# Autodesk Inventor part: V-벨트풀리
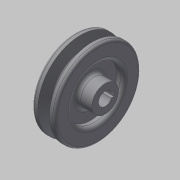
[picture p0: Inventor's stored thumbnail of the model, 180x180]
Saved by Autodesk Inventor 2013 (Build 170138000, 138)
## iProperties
Created: 2015-02
Part Number: V-벨트풀리
Material: 일반
Document SubType Name: Modeling
Designer: Administrator
Density: 1 g/cm^3
Author: Administrator
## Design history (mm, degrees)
sketch "스케치1"
  geometry: L1 (-12.5, 0)-(12.5, 0); L2 (-12.5, 11)-(-6.5, 11); L3 (-6.5, 11)-(-6.5, 21.5); L4 (-6.5, 21.5)-(-12.5, 21.5); L5 (-12.5, 21.5)-(-12.5, 35.2); L6 (-12.5, 35.2)-(-7.825, 35.2); L7 (-7.825, 35.2)-(-5.074, 26.2); L8 (-5.074, 26.2)-(-0.926, 26.2); L9 (-0.926, 26.2)-(1.825, 35.2); L10 (1.825, 35.2)-(6.5, 35.2); L11 (6.5, 35.2)-(6.5, 21.5); L12 (6.5, 21.5)-(0.5, 21.5); L13 (12.5, 5.5)-(-12.5, 5.5); L14 (-12.5, 11)-(-12.5, 5.5); L15 (0.5, 21.5)-(0.5, 11); L16 (0.5, 11)-(12.5, 11); L17 (12.5, 11)-(12.5, 5.5); L18 (-3, 26.2)-(-3, 25.898); L19 (-7, 32.5)-(1, 32.5); L20 (-3, 26.441)-(-3, 35.2); 10 further points
  constraints: 40 end point, 9 midpoint, 9 parallel, 6 perpendicular, 4 vertical alignment, 3 horizontal alignment, 2 coincident, 2 collinear, 2 point on line, 1 horizontal, 1 vertical, 1 other
  dimensions: "d0" = 25 distance of L1.start L1.end; "d2" = 34 deg angle of L9 L7; "d4" = 43 diameter of L4 L1; "d5" = 19 distance between parallel lines of L11 L5; "d6" = 6 distance of L2.start L2.end; "d7" = 6 distance of L11.end L12.end; "d11" = 22 diameter of L16 L1; "d12" = 11 diameter of L13 L1; "d13" = 65 diameter of L19 L1; "d14" = 6.3 distance between parallel lines of L19 L8; "d15" = 2.7 distance between parallel lines of L19 L6; "d16" = 8 distance of L19.start L19.end
revolve "회전1" sketch "스케치1" stored, may be unused: angle "d17" = 90 deg
fillet "모깎기1" dims "d18" = 3
fillet "모깎기2" dims "d19" = 3
fillet "모깎기3" dims "d20" = 3
fillet "모깎기4" dims "d21" = 2
fillet "모깎기5" dims "d22" = 1
sketch "스케치2"
  geometry: L1 (-2, 7.3)-(2, 7.3); L2 (2, 7.3)-(2, 5.123); L3 (-2, 5.123)-(-2, 7.3); L4 (0, 7.3)-(0, -5.5); C1 r 11 at (0, 0) reference; A1 r 5.5 centre (0, 0) between (0, -5.5) and (-2, 5.123) reference; A2 r 5.5 centre (0, 0) between (2, 5.123) and (-2, 5.123)
  constraints: 8 end point, 5 point on circle, 2 parallel, 1 centre point, 1 coincident, 1 horizontal, 1 midpoint, 1 perpendicular, 1 vertical alignment
  dimensions: "d23" = 4 distance of L1.start L1.end; "d25" = 12.8 distance of L4.start L4.end
extrude "돌출1" cut sketch "스케치2" stored distance "d26" = 10; taper "d27" = 0 deg
node "솔리드1"
